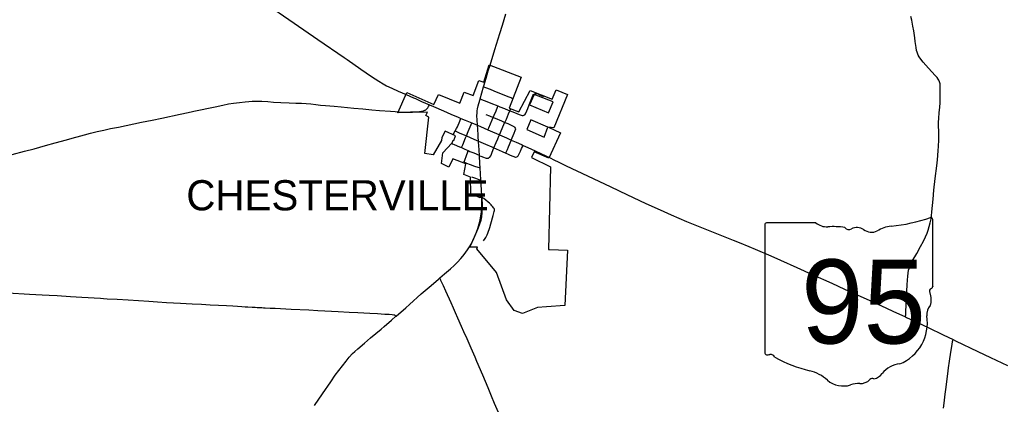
# Model space of a CAD drawing. Extents: x 9078 to 9739, y 4248 to 4966.
# Drawn here: x 9549.3 to 9630.7, y 4493.9 to 4525.8 of the extents above; entities that cross this region are included whole.
import ezdxf

# ---------------------------------------------------------------- set-up
doc = ezdxf.new("R2010")
doc.units = 0
for name, color, linetype in [('GM_X_City_Street', 7, 'Continuous'), ('GM_X_Corporation', 7, 'Continuous'), ('GM_X_Corporation_Text', 7, 'Continuous'), ('GM_X_County_Road', 7, 'Continuous'), ('GM_X_State_Route', 7, 'Continuous'), ('GM_X_State_Shield', 7, 'Continuous'), ('GM_X_Township_Road', 7, 'Continuous')]:
    doc.layers.add(name, color=color, linetype=linetype)

msp = doc.modelspace()

# ---------------------------------------------------------------- linework, layer by layer
at = {"layer": 'GM_X_City_Street'}
for points in [[(9587.803, 4520.222), (9587.96, 4520.165), (9588.351, 4520.025), (9588.66, 4519.903), (9589.122, 4519.717), (9589.895, 4519.412), (9590.051, 4519.353), (9590.125, 4519.318), (9590.193, 4519.276), (9590.239, 4519.237)], [(9589.979, 4518.238), (9590.146, 4518.19), (9590.377, 4518.099), (9590.756, 4517.932), (9590.831, 4517.899), (9590.909, 4517.869), (9590.99, 4517.849), (9591.072, 4517.847), (9591.15, 4517.872), (9591.217, 4517.92), (9591.268, 4517.985), (9591.306, 4518.059), (9591.466, 4518.441), (9591.588, 4518.748), (9591.795, 4519.287), (9591.857, 4519.44), (9591.894, 4519.515), (9591.942, 4519.582), (9592.005, 4519.635), (9592.08, 4519.667), (9592.161, 4519.678), (9592.244, 4519.67), (9592.323, 4519.647), (9592.474, 4519.578), (9592.769, 4519.428)], [(9580.745, 4518.153), (9581.242, 4518.14), (9581.74, 4518.145), (9582.153, 4518.161), (9582.481, 4518.183), (9582.644, 4518.203), (9582.724, 4518.217), (9582.801, 4518.239), (9582.877, 4518.267), (9582.919, 4518.285), (9582.955, 4518.304), (9583.003, 4518.333), (9583.06, 4518.378), (9583.114, 4518.428), (9583.162, 4518.482), (9583.206, 4518.541), (9583.242, 4518.604), (9583.32, 4518.736)], [(9587.519, 4519.228), (9587.638, 4519.188), (9587.852, 4519.106), (9588.079, 4519.021), (9588.548, 4518.827), (9588.847, 4518.698), (9588.984, 4518.641)], [(9588.602, 4517.697), (9588.678, 4517.872), (9588.833, 4518.24), (9588.946, 4518.54), (9588.984, 4518.641)], [(9588.984, 4518.641), (9589.149, 4518.574), (9589.526, 4518.424), (9589.827, 4518.298), (9589.979, 4518.238)], [(9587.997, 4517.946), (9588.3, 4517.821), (9588.602, 4517.697)], [(9589.568, 4517.283), (9589.687, 4517.558), (9589.875, 4517.996), (9589.979, 4518.238)], [(9589.979, 4518.238), (9589.983, 4518.249), (9590.062, 4518.437)], [(9585.433, 4516.574), (9585.546, 4516.77), (9585.629, 4516.926), (9585.698, 4517.064), (9585.778, 4517.255), (9585.83, 4517.39), (9585.896, 4517.563), (9585.914, 4517.613)], [(9586.385, 4516.156), (9586.525, 4516.525), (9586.771, 4517.114), (9586.82, 4517.232)], [(9588.156, 4516.666), (9588.231, 4516.84), (9588.516, 4517.505), (9588.602, 4517.697)], [(9588.602, 4517.697), (9588.75, 4517.636), (9589.276, 4517.413), (9589.568, 4517.283)], [(9589.12, 4516.244), (9589.197, 4516.436), (9589.548, 4517.237), (9589.568, 4517.283)], [(9589.568, 4517.283), (9589.801, 4517.18), (9590.098, 4517.046), (9590.245, 4516.976), (9590.313, 4516.932), (9590.372, 4516.877), (9590.417, 4516.809), (9590.447, 4516.741), (9590.457, 4516.686)], [(9585.264, 4516.287), (9585.433, 4516.574)], [(9585.433, 4516.574), (9585.563, 4516.514), (9585.784, 4516.411), (9586.385, 4516.156)], [(9585.974, 4515.192), (9586.068, 4515.433), (9586.308, 4515.996), (9586.385, 4516.156)], [(9586.385, 4516.156), (9586.985, 4515.901), (9587.377, 4515.732)], [(9588.655, 4515.173), (9588.847, 4515.627), (9588.97, 4515.912), (9589.078, 4516.151), (9589.12, 4516.244)], [(9590.094, 4515.817), (9590.326, 4516.376), (9590.424, 4516.597), (9590.457, 4516.686)], [(9585.145, 4515.537), (9585.158, 4515.524), (9585.185, 4515.51), (9585.22, 4515.495), (9585.354, 4515.443), (9585.808, 4515.261), (9585.974, 4515.192)], [(9587.377, 4515.732), (9587.952, 4515.476), (9588.47, 4515.255), (9588.655, 4515.173)], [(9589.647, 4514.726), (9589.683, 4514.817), (9589.777, 4515.029), (9589.864, 4515.243), (9590.079, 4515.781), (9590.094, 4515.817)], [(9590.472, 4514.4), (9590.553, 4514.416), (9590.623, 4514.459), (9590.674, 4514.522), (9590.75, 4514.669), (9590.852, 4514.9), (9590.95, 4515.13), (9591.02, 4515.267), (9591.076, 4515.379)], [(9585.974, 4515.192), (9586.241, 4515.067), (9586.526, 4514.941)], [(9586.202, 4513.988), (9586.196, 4514.009), (9586.196, 4514.028), (9586.199, 4514.057), (9586.206, 4514.081), (9586.412, 4514.61), (9586.466, 4514.766), (9586.526, 4514.941)], [(9586.526, 4514.941), (9586.67, 4514.878), (9586.919, 4514.776), (9587.13, 4514.692), (9587.23, 4514.655), (9587.305, 4514.623), (9587.369, 4514.589), (9587.452, 4514.523)], [(9587.452, 4514.523), (9587.558, 4514.482), (9587.794, 4514.394), (9587.937, 4514.348), (9588.012, 4514.328), (9588.088, 4514.314), (9588.128, 4514.312), (9588.177, 4514.314)], [(9588.177, 4514.314), (9588.215, 4514.328), (9588.268, 4514.36), (9588.323, 4514.412), (9588.388, 4514.502), (9588.451, 4514.654), (9588.513, 4514.805), (9588.655, 4515.173)], [(9588.655, 4515.173), (9588.832, 4515.092), (9589.347, 4514.857), (9589.647, 4514.726)], [(9589.647, 4514.726), (9589.782, 4514.666), (9590.006, 4514.577), (9590.232, 4514.482), (9590.442, 4514.402), (9590.472, 4514.4)], [(9586.202, 4513.988), (9586.388, 4513.911), (9586.692, 4513.783), (9587.039, 4513.651), (9587.316, 4513.56), (9587.512, 4513.508)], [(9586.793, 4512.757), (9587.032, 4512.68), (9587.121, 4512.652), (9587.412, 4512.558), (9587.578, 4512.508)], [(9587.783, 4507.479), (9587.937, 4507.667), (9587.982, 4507.734), (9588.021, 4507.805), (9588.086, 4507.952), (9588.142, 4508.105), (9588.304, 4508.563), (9588.404, 4508.871), (9588.607, 4509.572), (9588.69, 4509.886), (9588.706, 4509.983), (9588.695, 4510.055), (9588.664, 4510.138), (9588.623, 4510.21), (9588.556, 4510.292), (9588.49, 4510.374), (9588.415, 4510.456), (9588.303, 4510.574), (9588.182, 4510.682), (9587.997, 4510.84), (9587.82, 4510.978), (9587.775, 4511.008), (9587.74, 4511.016), (9587.666, 4511.016)]]:
    msp.add_lwpolyline(points, dxfattribs=at)
at = {"layer": 'GM_X_Corporation'}
for points in [[(9583.603, 4514.592), (9582.92, 4514.692), (9583.269, 4517.713), (9582.995, 4517.84), (9583.156, 4518.13), (9580.676, 4518.077), (9581.442, 4519.756), (9583.677, 4518.76), (9584.07, 4519.584), (9585.824, 4518.881), (9586.177, 4519.794), (9586.923, 4519.506), (9587.41, 4520.765), (9587.83, 4520.603), (9588.252, 4522.048), (9590.911, 4521.021), (9589.927, 4518.474), (9590.716, 4518.157), (9591.658, 4519.933), (9593.503, 4519.219), (9593.82, 4519.986), (9594.769, 4519.602), (9593.622, 4516.824), (9593.172, 4516.878), (9594.188, 4516.409), (9593.215, 4514.304), (9592.006, 4514.835), (9591.786, 4514.379), (9593.356, 4513.597), (9593.179, 4506.739), (9593.272, 4506.739), (9594.771, 4506.687), (9594.535, 4502.101), (9593.023, 4501.996), (9592.264, 4501.929), (9591.036, 4501.445), (9590.344, 4501.69), (9589.702, 4502.589), (9588.862, 4504.832), (9587.242, 4506.795), (9587.285, 4506.939), (9586.635, 4506.946), (9586.74, 4507.117), (9586.994, 4507.647), (9587.32, 4508.43), (9587.453, 4508.785), (9587.586, 4509.189), (9587.644, 4509.456), (9587.715, 4510.201), (9587.675, 4511.214), (9587.53, 4511.206), (9587.517, 4511.034), (9586.745, 4511.367), (9586.708, 4512.749), (9586.148, 4512.95), (9586.325, 4513.855), (9585.239, 4514.271), (9584.916, 4513.578), (9584.3, 4513.878), (9584.426, 4514.769), (9585.165, 4515.563), (9585.183, 4515.581), (9585.288, 4515.808), (9585.334, 4515.785), (9585.479, 4516.176), (9584.616, 4516.542), (9584.33, 4516.039), (9584.303, 4515.777)], [(9591.622, 4518.726), (9593.196, 4518.076), (9593.568, 4518.978), (9591.994, 4519.587)], [(9591.382, 4516.688), (9592.812, 4516.046), (9593.135, 4516.892), (9591.709, 4517.481)]]:
    msp.add_lwpolyline(points, close=True, dxfattribs=at)
at = {"layer": 'GM_X_County_Road'}
for points in [[(9563.655, 4518.177), (9563.761, 4518.199), (9565.526, 4518.574), (9566.167, 4518.711), (9566.649, 4518.808), (9567.053, 4518.877), (9567.542, 4518.943), (9568.032, 4518.993), (9568.327, 4519.016)], [(9568.327, 4519.016), (9568.605, 4519.037), (9568.852, 4519.047), (9569.18, 4519.041), (9569.407, 4519.036), (9569.908, 4519.005), (9570.367, 4518.971), (9570.982, 4518.934), (9571.66, 4518.903), (9572.21, 4518.888), (9572.696, 4518.873), (9573.08, 4518.852), (9573.474, 4518.816), (9573.869, 4518.775), (9574.275, 4518.72), (9574.681, 4518.68), (9575.412, 4518.617), (9575.983, 4518.564), (9577.044, 4518.463), (9577.779, 4518.394), (9578.514, 4518.326), (9579.167, 4518.266), (9580.066, 4518.203), (9580.475, 4518.172), (9580.745, 4518.153)], [(9548.689, 4514.616), (9549.72, 4514.89), (9550.512, 4515.101), (9551.461, 4515.363), (9552.251, 4515.582), (9553.201, 4515.84), (9553.676, 4515.968), (9554.386, 4516.166), (9554.702, 4516.254), (9555.177, 4516.383), (9555.733, 4516.525), (9556.293, 4516.65), (9556.855, 4516.766), (9557.498, 4516.897), (9558.783, 4517.163), (9559.426, 4517.295), (9560.311, 4517.473), (9561.113, 4517.642), (9562.639, 4517.959), (9563.28, 4518.098), (9563.655, 4518.177)], [(9625.963, 4493.608), (9626.009, 4494.015), (9626.094, 4494.746), (9626.148, 4495.152), (9626.322, 4496.45), (9626.384, 4496.938), (9626.457, 4497.506), (9626.565, 4498.235), (9626.673, 4498.882), (9626.717, 4499.123), (9626.748, 4499.287)]]:
    msp.add_lwpolyline(points, dxfattribs=at)
at = {"layer": 'GM_X_State_Route'}
for points in [[(9552.473, 4538.913), (9552.784, 4538.7), (9553.734, 4538.055), (9555.428, 4536.899), (9556.65, 4536.07), (9557.802, 4535.285), (9559.365, 4534.229), (9560.991, 4533.12), (9562.212, 4532.288), (9563.499, 4531.411), (9564.45, 4530.767), (9566.072, 4529.652), (9567.221, 4528.862), (9568.708, 4527.839), (9569.516, 4527.278), (9572.084, 4525.511), (9574.046, 4524.166), (9576.228, 4522.664)], [(9588.336, 4522.031), (9588.739, 4523.315), (9589.146, 4524.645), (9589.358, 4525.35), (9589.635, 4526.291)], [(9576.228, 4522.664), (9576.478, 4522.492), (9577.622, 4521.694), (9578.503, 4521.095), (9579.121, 4520.693), (9579.471, 4520.481), (9579.758, 4520.325), (9580.198, 4520.107), (9580.72, 4519.869), (9581.38, 4519.584)], [(9587.286, 4517.042), (9587.26, 4517.49), (9587.248, 4517.821), (9587.253, 4518.07), (9587.27, 4518.236), (9587.297, 4518.4), (9587.354, 4518.642), (9587.487, 4519.117), (9587.519, 4519.228), (9587.803, 4520.222), (9587.85, 4520.386), (9587.908, 4520.578), (9588.011, 4520.935), (9588.188, 4521.562), (9588.336, 4522.031)], [(9581.38, 4519.584), (9581.976, 4519.33), (9582.148, 4519.252)], [(9582.148, 4519.252), (9582.658, 4519.021), (9583.32, 4518.736), (9583.631, 4518.601), (9584.478, 4518.233), (9585.078, 4517.974), (9585.679, 4517.715), (9585.914, 4517.613), (9586.278, 4517.456), (9586.82, 4517.232), (9587.286, 4517.042)], [(9587.286, 4517.042), (9587.852, 4516.797), (9588.156, 4516.666), (9588.342, 4516.585), (9589.054, 4516.273), (9589.12, 4516.244), (9589.703, 4515.991), (9590.094, 4515.817), (9590.501, 4515.635), (9590.948, 4515.438), (9591.076, 4515.379), (9591.467, 4515.199), (9592.065, 4514.926), (9592.556, 4514.696), (9593.255, 4514.362)], [(9587.353, 4516.072), (9587.342, 4516.228), (9587.309, 4516.716), (9587.286, 4517.042)], [(9587.656, 4511.208), (9587.632, 4511.693), (9587.578, 4512.508), (9587.545, 4513.007), (9587.512, 4513.508), (9587.487, 4513.888), (9587.452, 4514.523), (9587.428, 4515.02), (9587.385, 4515.665), (9587.377, 4515.732), (9587.353, 4516.072)], [(9593.255, 4514.362), (9593.692, 4514.155), (9593.992, 4514.01), (9594.658, 4513.692), (9595.548, 4513.273), (9596.902, 4512.626)], [(9596.902, 4512.626), (9598.359, 4511.93), (9599.692, 4511.294), (9601.254, 4510.57), (9602.45, 4510.029), (9603.349, 4509.628), (9604.629, 4509.075), (9605.462, 4508.728), (9606.835, 4508.184), (9607.673, 4507.851), (9608.511, 4507.516), (9609.011, 4507.318)], [(9586.62, 4506.96), (9586.76, 4507.203), (9586.914, 4507.495), (9587.055, 4507.794), (9587.212, 4508.175), (9587.321, 4508.486), (9587.437, 4508.882), (9587.513, 4509.203), (9587.573, 4509.528), (9587.618, 4509.854), (9587.643, 4510.183), (9587.667, 4510.761), (9587.666, 4511.016), (9587.656, 4511.208)], [(9609.011, 4507.318), (9609.807, 4507.003), (9610.338, 4506.786), (9611.618, 4506.236), (9612.44, 4505.865), (9613.789, 4505.264), (9615.057, 4504.685), (9616.702, 4503.944), (9617.747, 4503.468), (9618.789, 4502.987), (9619.834, 4502.512), (9621.179, 4501.903), (9621.815, 4501.615)], [(9584.173, 4504.395), (9584.554, 4504.722), (9585.054, 4505.147), (9585.356, 4505.422), (9585.646, 4505.711), (9585.925, 4506.01), (9586.085, 4506.196), (9586.283, 4506.455), (9586.514, 4506.793), (9586.62, 4506.96)], [(9573.783, 4493.819), (9574.423, 4494.772), (9575.117, 4495.788), (9575.498, 4496.323), (9576.088, 4497.112), (9576.392, 4497.5), (9576.657, 4497.813), (9576.935, 4498.115), (9577.11, 4498.29), (9577.353, 4498.512), (9577.913, 4498.993), (9578.416, 4499.416), (9579.292, 4500.157), (9579.541, 4500.37), (9580.164, 4500.902), (9580.528, 4501.217), (9580.536, 4501.224), (9581.339, 4501.925), (9581.646, 4502.198), (9582.631, 4503.06), (9583.439, 4503.756), (9584.056, 4504.294), (9584.173, 4504.395)], [(9621.815, 4501.615), (9622, 4501.531), (9622.798, 4501.163), (9622.894, 4501.118), (9623.86, 4500.669), (9624.673, 4500.28), (9625.93, 4499.677), (9626.748, 4499.287), (9626.966, 4499.183), (9628.814, 4498.294), (9629.85, 4497.798), (9631.256, 4497.128)]]:
    msp.add_lwpolyline(points, dxfattribs=at)
at = {"layer": 'GM_X_State_Shield'}
for p, q in [((9615.353, 4508.96), (9611.276, 4508.96)), ((9625.06, 4503.694), (9625.06, 4509.222)), ((9611.139, 4508.778), (9611.139, 4498.212)), ((9625.059, 4503.696), (9625.06, 4503.694))]:
    msp.add_line(p, q, dxfattribs=at)
for centre, radius, start, end in [((9611.298, 4508.801), 0.161, 98.1301, 188.1301), ((9616.324, 4510.187), 1.564, 231.61951, 271.11188), ((9620.101, 4523.365), 14.764, 275.84447, 288.90645), ((9624.906, 4509.245), 0.155, 351.86209, 97.738), ((9616.842, 4503.028), 5.616, 80.48669, 94.98827), ((9618.117, 4508.855), 0.451, 219.79206, 297.10237), ((9618.78, 4507.634), 0.938, 54.46668, 119.14113), ((9619.991, 4509.309), 1.129, 233.85621, 294.82819), ((9621.984, 4505.733), 2.97, 97.34618, 120.76885), ((9625.025, 4503.289), 0.24, 107.94398, 210.33697), ((9623.499, 4502.59), 1.44, 340.03296, 23.64957), ((9624.895, 4503.673), 0.166, 289.60381, 7.73413), ((9625.616, 4501.381), 1.048, 136.8065, 186.92959), ((9620.928, 4500.678), 3.693, 292.30889, 8.98584), ((9611.3, 4498.189), 0.163, 171.95839, 258.30661), ((9611.324, 4499.27), 1.242, 267.33899, 280.60386), ((9611.578, 4497.602), 0.448, 29.74838, 93.27175), ((9617.231, 4507.096), 10.661, 240.41292, 257.1985), ((9614.053, 4493.465), 3.336, 47.18416, 75.83597), ((9622.485, 4495.245), 2.022, 94.40312, 142.57675), ((9617.66, 4497.55), 2.117, 230.70037, 286.29184), ((9619.038, 4496.758), 1.128, 268.77702, 315.54927), ((9620.058, 4495.735), 0.318, 65.75173, 132.64842), ((9619.923, 4497.188), 1.193, 282.87319, 323.27711), ((9618.883, 4493.897), 1.739, 85.69512, 111.20995)]:
    msp.add_arc(centre, radius, start, end, dxfattribs=at)
at = {"layer": 'GM_X_Township_Road'}
for points in [[(9622.798, 4501.163), (9622.819, 4501.349), (9622.837, 4501.512), (9622.872, 4502.249), (9622.936, 4503.806), (9622.957, 4504.216), (9622.984, 4504.543), (9623.016, 4504.786), (9623.063, 4505.028), (9623.106, 4505.186), (9623.158, 4505.342), (9623.256, 4505.567), (9623.369, 4505.785), (9623.737, 4506.426), (9624.059, 4506.998), (9624.288, 4507.434), (9624.464, 4507.804), (9624.591, 4508.106), (9624.676, 4508.337), (9624.773, 4508.65), (9624.856, 4508.968), (9624.926, 4509.289), (9624.964, 4509.531), (9624.997, 4509.858), (9625.086, 4510.92), (9625.157, 4511.655), (9625.272, 4512.633), (9625.408, 4513.69), (9625.456, 4514.18), (9625.508, 4514.916), (9625.546, 4515.323), (9625.568, 4515.814), (9625.573, 4516.143), (9625.56, 4516.552), (9625.545, 4516.961), (9625.547, 4517.289), (9625.562, 4517.616), (9625.603, 4518.106), (9625.642, 4518.514), (9625.668, 4518.923), (9625.679, 4519.251), (9625.691, 4520.236), (9625.68, 4520.399), (9625.667, 4520.48), (9625.649, 4520.56), (9625.626, 4520.638), (9625.596, 4520.715), (9625.561, 4520.789), (9625.52, 4520.859), (9625.424, 4520.993), (9625.265, 4521.18), (9624.989, 4521.484), (9624.711, 4521.785), (9624.493, 4522.029), (9624.281, 4522.277), (9624.08, 4522.531), (9623.94, 4522.729), (9623.856, 4522.867), (9623.82, 4522.938), (9623.788, 4523.013), (9623.761, 4523.09), (9623.72, 4523.248), (9623.676, 4523.49), (9623.617, 4523.976), (9623.576, 4524.299), (9623.484, 4524.86), (9623.417, 4525.262), (9623.328, 4525.745), (9623.256, 4526.064)], [(9589.033, 4493.231), (9588.704, 4493.981), (9588.457, 4494.587), (9588.179, 4495.269), (9587.954, 4495.796), (9587.73, 4496.323), (9587.25, 4497.455), (9587.09, 4497.833), (9586.764, 4498.583), (9586.435, 4499.333), (9586.165, 4499.931), (9585.964, 4500.379), (9585.668, 4501.054), (9585.465, 4501.502), (9585.299, 4501.876), (9585.098, 4502.325), (9584.663, 4503.294), (9584.461, 4503.741), (9584.263, 4504.191), (9584.173, 4504.395)], [(9548.32, 4503.154), (9550.123, 4503.054), (9551.187, 4502.995), (9551.761, 4502.962), (9552.416, 4502.922), (9553.529, 4502.862), (9554.464, 4502.807), (9556.014, 4502.718), (9556.255, 4502.694), (9556.582, 4502.669), (9557.4, 4502.62), (9558.301, 4502.568), (9560.021, 4502.459), (9560.758, 4502.408), (9561.494, 4502.363), (9562.067, 4502.325), (9562.64, 4502.293), (9563.131, 4502.263), (9563.621, 4502.235), (9564.398, 4502.212), (9565.106, 4502.175), (9565.815, 4502.138), (9566.46, 4502.107), (9566.988, 4502.075), (9567.379, 4502.049), (9567.739, 4502.028), (9568.019, 4502.006), (9568.252, 4501.991), (9568.601, 4501.975), (9568.849, 4501.959), (9569.013, 4501.948), (9569.214, 4501.933), (9569.396, 4501.928), (9569.538, 4501.92), (9569.668, 4501.914), (9570.106, 4501.888), (9570.512, 4501.876), (9571.83, 4501.81), (9573.306, 4501.738), (9574.057, 4501.696), (9574.637, 4501.661), (9575.736, 4501.602), (9576.646, 4501.558), (9577.355, 4501.521), (9577.862, 4501.494), (9578.364, 4501.468), (9579.004, 4501.431), (9579.594, 4501.393), (9579.964, 4501.379), (9580.222, 4501.365), (9580.344, 4501.339), (9580.408, 4501.321), (9580.454, 4501.281), (9580.528, 4501.217)]]:
    msp.add_lwpolyline(points, dxfattribs=at)

# ---------------------------------------------------------------- texts
at = {"layer": 'GM_X_Corporation_Text'}
msp.add_text('CHESTERVILLE', height=2.5, rotation=0.00001, dxfattribs=at).set_placement((9563.136, 4509.992))
at = {"layer": 'GM_X_State_Shield'}
msp.add_text('95', height=6.961, dxfattribs=at).set_placement((9614.142, 4498.957))

doc.saveas('drawing.dxf')
